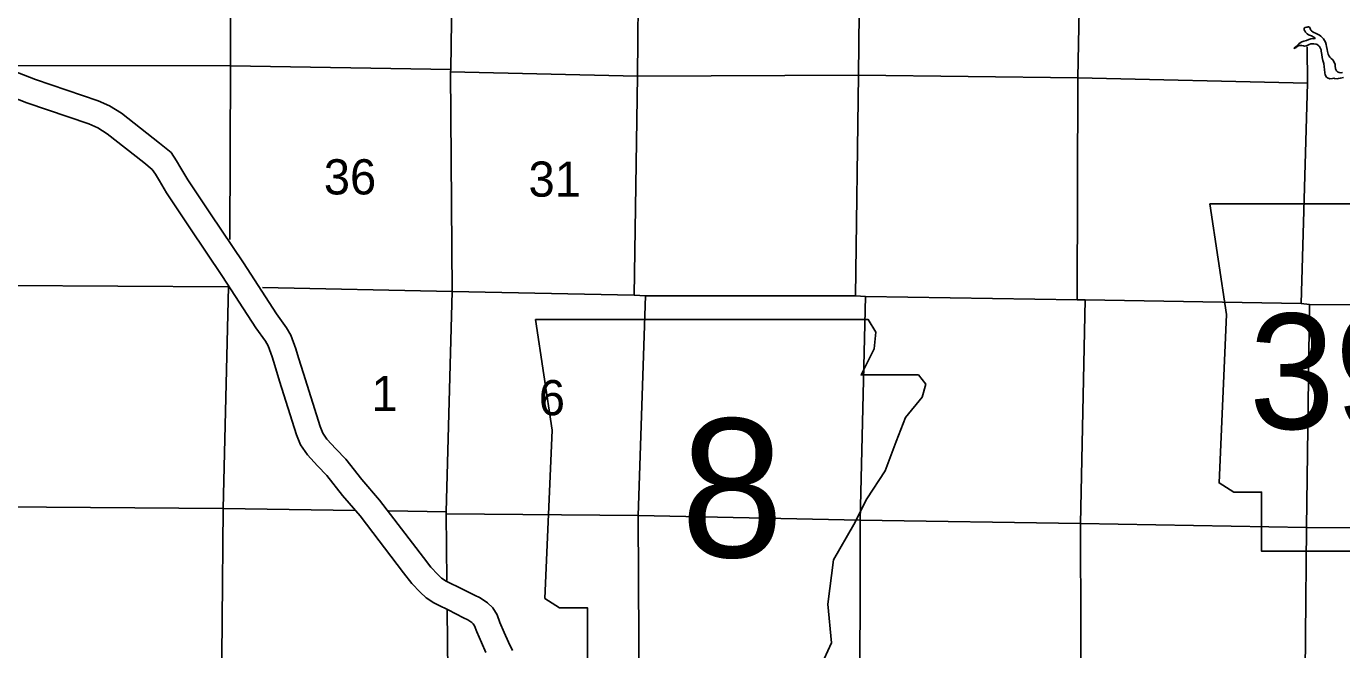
# Model space of a CAD drawing. Extents: x 369523 to 838377, y 495025 to 936819.
# Drawn here: x 538589 to 570168, y 785066 to 800042 of the extents above; entities that cross this region are included whole.
import ezdxf

# ---------------------------------------------------------------- set-up
doc = ezdxf.new("R2010")
doc.units = 0
for name, color, linetype in [('22', 7, 'Continuous'), ('Level 1', 7, 'Continuous'), ('Level 10', 7, 'Continuous'), ('Level 15', 7, 'Continuous'), ('Level 22', 7, 'Continuous')]:
    doc.layers.add(name, color=color, linetype=linetype)

msp = doc.modelspace()

# ---------------------------------------------------------------- linework, layer by layer
at = {"layer": '22'}
for points in [[(567003, 795779), (567402, 793115), (567225, 789073), (567580, 788851), (568246, 788851), (568246, 787430), (573842, 787430), (574108, 788007), (574019, 788940), (574153, 790006), (574641, 790850), (574952, 791471), (575396, 792138), (575662, 792848), (575884, 793425), (576284, 793914), (576373, 794225), (576195, 794447), (574819, 794447), (575130, 795069), (575174, 795468), (574990, 795775)], [(550815, 793001), (551215, 790337), (551037, 786296), (551392, 786073), (552059, 786073), (552059, 784652), (557654, 784652), (557921, 785230), (557832, 786162), (557965, 787228), (558454, 788072), (558764, 788694), (559208, 789360), (559475, 790070), (559697, 790648), (560097, 791136), (560185, 791447), (560008, 791669), (558631, 791669), (558942, 792291), (558986, 792691), (558802, 792997)]]:
    msp.add_lwpolyline(points, close=True, dxfattribs=at)
at = {"layer": 'Level 1'}
for points in [[(550258, 785048), (550169, 785244), (550063, 785483), (549959, 785719), (549890, 785900), (549787, 786074), (549659, 786189), (549488, 786308), (549347, 786372), (548985, 786557), (548748, 786675), (548665, 786716), (548559, 786783), (548471, 786869), (548299, 787047), (548121, 787279), (547070, 788657), (546644, 789151), (546262, 789640), (546020, 789895), (545806, 790121), (545706, 790270), (545645, 790428), (545242, 791699), (545127, 792075), (545056, 792296), (544940, 792619), (544833, 792802), (544598, 793133), (543803, 794362), (543012, 795534), (542466, 796354), (542303, 796636), (542194, 796812), (542064, 797007), (541787, 797234), (540872, 797954), (540586, 798130), (540313, 798254), (538808, 798765), (538126, 799031)], [(549621, 784999), (549514, 785241), (549404, 785492), (549348, 785639), (549318, 785689), (549286, 785717), (549189, 785785), (549086, 785832), (548715, 786021), (548481, 786138), (548371, 786192), (548185, 786309), (548045, 786446), (547844, 786655), (547644, 786914), (546604, 788279), (546180, 788770), (545807, 789248), (545584, 789483), (545336, 789744), (545171, 789991), (545079, 790229), (544670, 791520), (544555, 791896), (544488, 792103), (544394, 792364), (544328, 792476), (544102, 792796), (543302, 794032), (542514, 795200), (541956, 796038), (541789, 796327), (541689, 796487), (541614, 796600), (541411, 796767), (540527, 797462), (540304, 797600), (540093, 797695), (538603, 798201), (537901, 798475)]]:
    msp.add_lwpolyline(points, dxfattribs=at)
at = {"layer": 'Level 10'}
for points in [[(570211, 798810), (570137, 798797), (570086, 798784), (570072, 798782), (569996, 798792), (569978, 798794), (569944, 798787), (569884, 798780), (569830, 798801), (569800, 798823), (569771, 798874), (569762, 798924), (569754, 799008), (569749, 799072), (569740, 799146), (569718, 799224), (569697, 799289), (569690, 799365), (569677, 799441), (569672, 799479), (569653, 799525), (569633, 799553), (569616, 799576), (569582, 799606), (569554, 799611), (569496, 799620), (569428, 799617), (569390, 799608), (569354, 799590), (569319, 799575), (569275, 799568), (569253, 799574), (569209, 799579), (569181, 799578), (569143, 799578), (569125, 799571), (569094, 799549), (569074, 799536), (569052, 799524), (569040, 799516), (569028, 799512), (569028, 799518), (569074, 799554), (569115, 799597), (569136, 799622), (569172, 799648), (569209, 799667), (569263, 799684), (569322, 799703), (569376, 799722), (569424, 799739), (569457, 799746), (569501, 799744), (569511, 799745), (569519, 799745), (569525, 799747), (569529, 799751), (569523, 799765), (569509, 799775), (569497, 799784), (569444, 799813), (569398, 799833), (569368, 799840), (569338, 799858), (569321, 799879), (569303, 799901), (569280, 799931), (569276, 799939), (569266, 799956), (569268, 799973), (569271, 799985), (569277, 800003), (569287, 800013), (569321, 800020), (569337, 800022), (569363, 800026), (569374, 800026), (569386, 800025), (569407, 800011), (569413, 799993), (569416, 799965), (569424, 799947), (569444, 799930), (569481, 799904), (569553, 799870), (569634, 799831), (569670, 799804)], [(569670, 799804), (569731, 799741), (569776, 799659), (569793, 799602), (569804, 799556), (569818, 799482), (569826, 799438), (569845, 799376), (569868, 799321), (569883, 799299), (569913, 799267), (569952, 799234), (569983, 799194), (570014, 799121), (570014, 799089), (570020, 799023), (570042, 798973), (570069, 798948), (570109, 798932), (570149, 798921), (570187, 798930)]]:
    msp.add_lwpolyline(points, dxfattribs=at)
at = {"layer": 'Level 15'}
for points in [[(548683, 786732), (548665, 788326), (548665, 788380), (548809, 793675), (548776, 798946), (548778, 799006), (548857, 804231), (548862, 804313), (548925, 809508), (548929, 809576), (549043, 814455)], [(543433, 793786), (538135, 793819), (538103, 793817), (532856, 793908), (532802, 793904)], [(569193, 793381), (564012, 793468), (563820, 793471), (558738, 793547), (558499, 793568), (553455, 793570), (553184, 793581), (548809, 793675), (544257, 793767)], [(581650, 793273), (579795, 793284), (574667, 793322), (574489, 793316), (569397, 793359), (569193, 793381)], [(548578, 777786), (548724, 783056), (548691, 786013)]]:
    msp.add_lwpolyline(points, dxfattribs=at)
at = {"layer": 'Level 22'}
for points in [[(553420, 817087), (553406, 814715), (553358, 809312), (553313, 804107), (553265, 798842), (553184, 793581)], [(543475, 794917), (543495, 799095), (543490, 804340), (543538, 809653), (543641, 814890), (543628, 815100)], [(558499, 793568), (558567, 798867), (558622, 804090), (558779, 809361), (558712, 814544)], [(564006, 813704), (564093, 809429), (563941, 804133), (563832, 798802), (563820, 793471)], [(569193, 793381), (569345, 798672), (569339, 799549)], [(548778, 799006), (543495, 799095), (538188, 799100), (538035, 799102)], [(569345, 798672), (563832, 798802), (558567, 798867), (553265, 798842), (548776, 798946)], [(543253, 777817), (543269, 783108), (543312, 788455), (543444, 793786)], [(553455, 793570), (553275, 788287), (553300, 783762)], [(558575, 781223), (558603, 782903), (558608, 788180), (558738, 793547)], [(564012, 793468), (563899, 788097), (563916, 782846), (563876, 779465)], [(569397, 793359), (569322, 788005), (569275, 782781), (569183, 778436)], [(546485, 788411), (543312, 788455), (538011, 788498), (532707, 788583)], [(548665, 788380), (547295, 788399)], [(569322, 788005), (563899, 788097), (558608, 788180), (553275, 788287), (548665, 788326)], [(580989, 787945), (579758, 787955), (574582, 787973), (569322, 788005)]]:
    msp.add_lwpolyline(points, dxfattribs=at)

# ---------------------------------------------------------------- texts
at = {"layer": '22'}
for s, height, p in [('390', 2772, (567942, 790369)), ('8', 3326, (554297, 787289))]:
    msp.add_text(s, height=height, dxfattribs=at).set_placement(p)
at = {"layer": 'Level 22'}
for s, height, p in [('36', 844.8, (545732, 796003)), ('31', 844.8, (550646, 795949)), ('1', 845, (546875, 790799)), ('6', 845, (550893, 790698))]:
    msp.add_text(s, height=height, dxfattribs=at).set_placement(p)

doc.saveas('drawing.dxf')
